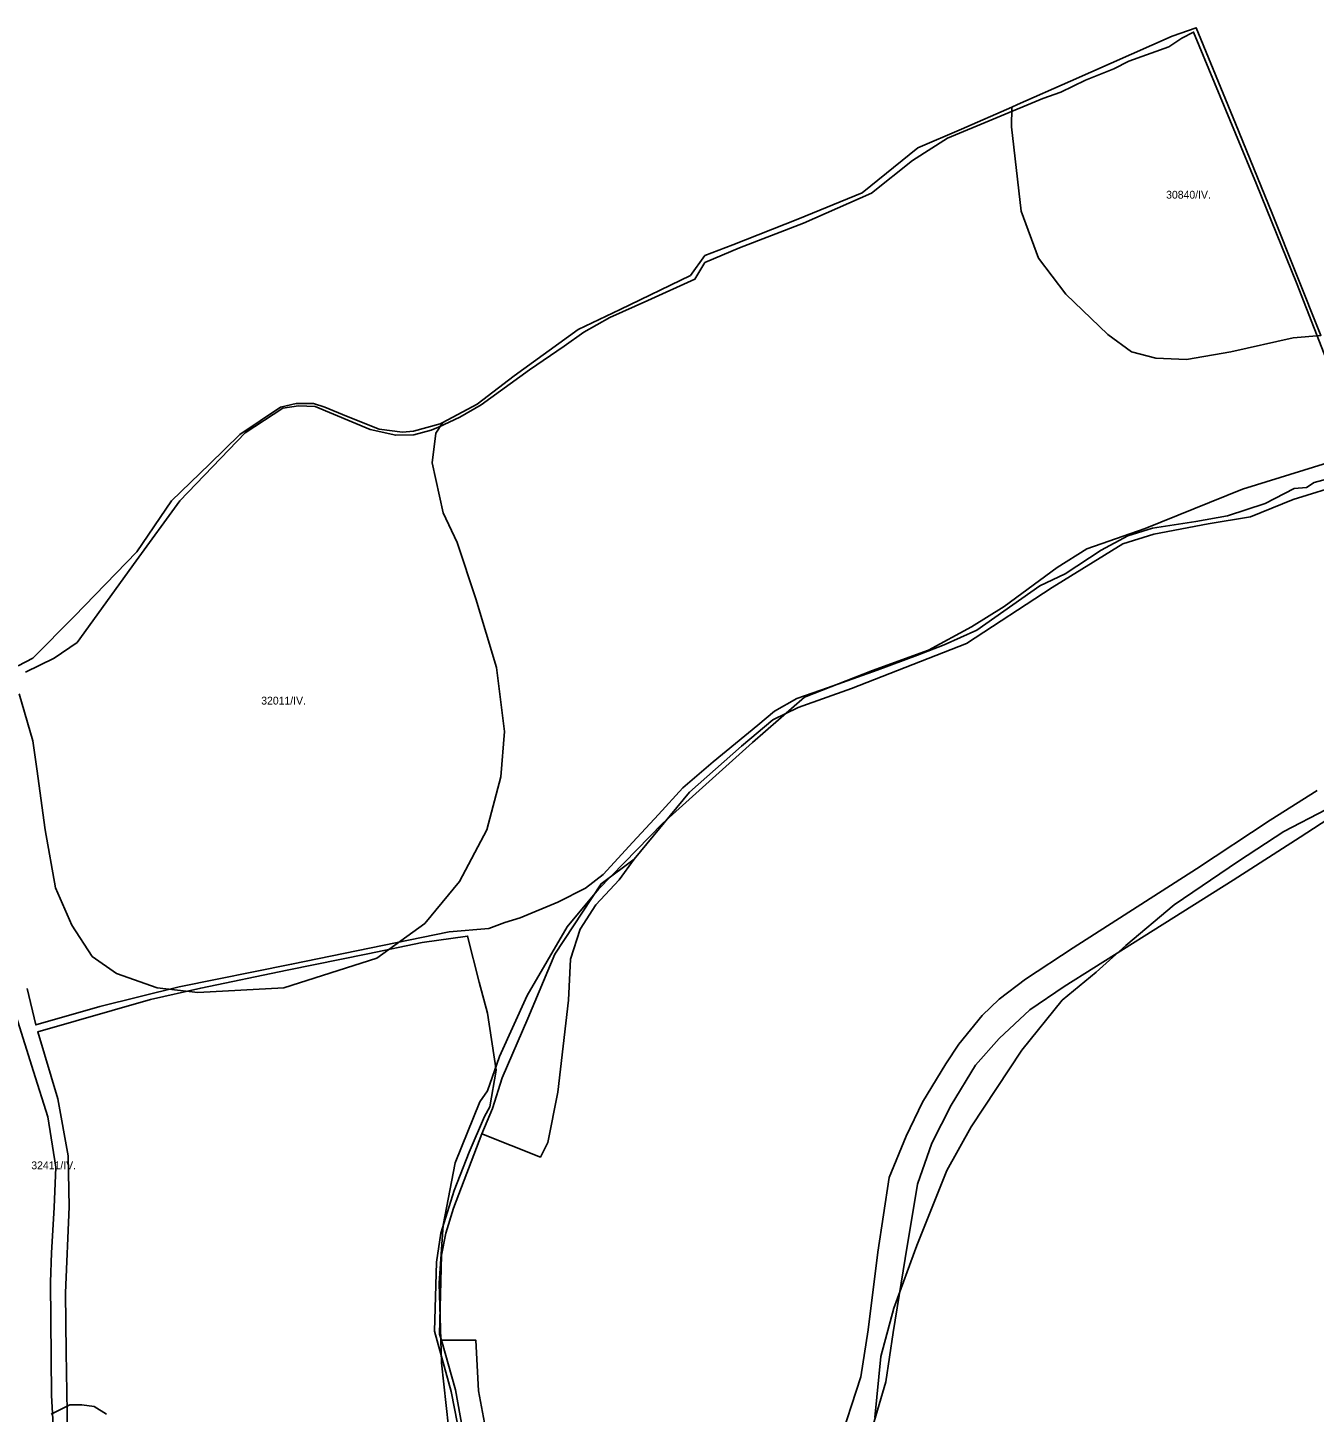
# Model space of a CAD drawing. Extents: x -532083 to -529270, y -1180561 to -1176456.
# Drawn here: x -531031 to -530208, y -1177342 to -1176456 of the extents above; entities that cross this region are included whole.
import ezdxf

# ---------------------------------------------------------------- set-up
doc = ezdxf.new("R2010")
doc.units = 0
for name, color, linetype in [('95560013', 7, 'Continuous'), ('95620013', 7, 'Continuous'), ('95660013', 7, 'Continuous')]:
    doc.layers.add(name, color=color, linetype=linetype)

msp = doc.modelspace()

# ---------------------------------------------------------------- linework, layer by layer
at = {"layer": '95560013'}
for points in [[(-531032.6033, -1176868.07145), (-531014.2283, -1176859.15945), (-530999.4883, -1176849.03245), (-530961.8023, -1176796.80545), (-530933.9613, -1176758.42645), (-530892.0933, -1176714.76745), (-530867.9773, -1176699.04445), (-530857.8783, -1176697.53245), (-530847.3283, -1176697.98545), (-530812.1553, -1176712.75345), (-530795.7153, -1176716.36145), (-530784.0703, -1176716.18945), (-530772.9393, -1176713.09745), (-530768.3153, -1176711.20745), (-530754.6163, -1176704.85245), (-530740.9163, -1176696.95045), (-530710.0913, -1176674.44745), (-530687.8533, -1176659.43745), (-530675.3193, -1176650.36945), (-530658.6773, -1176641.09545), (-530634.4323, -1176630.17245), (-530604.2293, -1176616.56945), (-530597.8603, -1176605.85345), (-530575.7753, -1176596.39745), (-530534.6893, -1176580.56545), (-530491.0983, -1176561.46745), (-530465.0443, -1176540.61045), (-530442.4973, -1176526.28645), (-530381.5713, -1176500.80145), (-530369.9723, -1176496.85745), (-530354.2443, -1176489.16645), (-530336.1573, -1176481.87045), (-530326.5243, -1176476.94045), (-530300.9663, -1176467.86945), (-530292.5133, -1176462.15045), (-530285.0423, -1176458.40345), (-530244.8243, -1176555.64745), (-530219.0883, -1176618.78145), (-530190.1893, -1176693.25345)], [(-530173.8473, -1176737.54745), (-530207.9223, -1176746.61545), (-530212.7903, -1176749.75445), (-530220.6143, -1176750.45245), (-530239.2163, -1176760.04345), (-530263.4073, -1176767.95345), (-530283.6703, -1176771.51545), (-530311.2443, -1176775.91545), (-530327.1203, -1176780.73545), (-530344.2503, -1176789.95445), (-530367.2283, -1176805.04145), (-530383.5223, -1176812.79445), (-530423.7443, -1176841.13645), (-530444.7393, -1176850.58645), (-530461.6973, -1176857.06645), (-530487.5383, -1176866.78745), (-530519.3013, -1176878.12745), (-530538.9513, -1176884.87745), (-530553.2173, -1176892.97745), (-530563.9843, -1176901.88745), (-530592.5173, -1176925.37745), (-530611.8973, -1176942.11845), (-530627.5313, -1176959.11045), (-530643.8413, -1176976.90845), (-530663.0183, -1176997.58245), (-530674.3093, -1177006.39145), (-530691.8723, -1177015.20045), (-530716.0683, -1177025.26745), (-530725.9253, -1177028.32345), (-530736.1553, -1177032.04745), (-530761.3993, -1177034.12845), (-530862.3733, -1177054.94045), (-530934.3013, -1177069.50945), (-530985.1343, -1177081.99645), (-531026.1123, -1177093.83845), (-531031.6673, -1177070.43545)], [(-530738.3213, -1177351.91345), (-530742.6713, -1177327.91645), (-530744.3633, -1177295.67845), (-530766.3533, -1177295.67845), (-530767.7883, -1177291.65545), (-530767.0563, -1177266.43445), (-530766.3243, -1177241.21445), (-530763.6393, -1177227.01245), (-530758.7563, -1177211.09645), (-530740.6923, -1177163.59445), (-530703.0453, -1177178.44445), (-530698.4073, -1177169.14045), (-530691.9853, -1177136.93445), (-530685.2073, -1177077.89045), (-530683.7803, -1177051.76745), (-530677.7163, -1177032.44445), (-530667.7273, -1177017.05645), (-530652.7433, -1177000.95345), (-530643.1113, -1176987.71345), (-530607.5943, -1176944.85845), (-530574.4383, -1176915.34545), (-530554.2373, -1176898.60645), (-530538.2083, -1176890.67745), (-530503.9553, -1176878.56345), (-530430.3583, -1176849.77845), (-530375.6313, -1176813.86345), (-530330.4023, -1176785.82645), (-530310.5013, -1176779.79645), (-530275.6753, -1176773.14245), (-530248.5193, -1176768.56745), (-530221.3573, -1176757.56345), (-530188.3163, -1176747.18245)], [(-530490.6373, -1177351.35145), (-530481.9833, -1177322.15245), (-530477.2563, -1177290.69245), (-530469.5993, -1177243.23545), (-530461.6683, -1177195.77945), (-530452.6443, -1177169.44545), (-530440.2693, -1177145.16045), (-530424.5623, -1177119.55645), (-530409.5093, -1177102.48845), (-530389.8753, -1177084.10645), (-530367.8413, -1177069.22645), (-530310.9193, -1177033.44145), (-530259.8063, -1177001.26645), (-530216.7773, -1176973.53945), (-530159.4063, -1176936.39445)], [(-530205.9203, -1176943.67145), (-530236.1413, -1176962.81445), (-530283.1843, -1176993.94545), (-530362.1843, -1177044.41145), (-530392.5373, -1177064.43045), (-530409.5853, -1177077.36045), (-530420.3953, -1177087.78645), (-530435.3643, -1177106.13845), (-530443.6803, -1177118.65045), (-530458.6483, -1177143.25745), (-530469.0433, -1177164.94545), (-530479.9283, -1177191.48345), (-530487.1233, -1177239.29545), (-530493.4183, -1177288.91245), (-530497.9153, -1177319.13345), (-530512.7543, -1177364.23845)], [(-531005.7623, -1177354.41745), (-531006.6203, -1177303.21945), (-531007.0673, -1177265.32145), (-531004.6083, -1177210.15545), (-531005.4483, -1177177.64145), (-531011.8923, -1177141.08845), (-531024.7793, -1177098.29545), (-530952.6283, -1177077.48645), (-530920.4683, -1177070.20245), (-530865.1403, -1177058.75645), (-530813.6153, -1177048.35045), (-530778.6893, -1177041.06545), (-530749.7013, -1177036.94645), (-530742.3883, -1177066.49945), (-530736.9553, -1177086.20145), (-530731.3133, -1177122.67145), (-530735.4923, -1177146.14645), (-530738.8923, -1177152.46045), (-530748.7013, -1177175.24545), (-530758.2523, -1177199.84445), (-530766.7703, -1177227.03145), (-530769.6093, -1177245.67445), (-530770.9653, -1177289.89945), (-530760.1993, -1177328.34445), (-530756.1083, -1177349.07945)], [(-531043.1993, -1177073.95245), (-531027.6233, -1177123.57445), (-531018.2733, -1177152.67245), (-531013.2393, -1177184.89645), (-531014.1983, -1177210.62345), (-531016.1163, -1177239.72145), (-531016.5953, -1177258.47845), (-531016.1163, -1177330.85845), (-531013.9583, -1177369.33145)], [(-530753.0623, -1177352.39845), (-530757.4123, -1177327.43145), (-530766.3533, -1177295.67845), (-530744.3633, -1177295.67845), (-530742.6713, -1177327.91645), (-530738.3213, -1177351.91345)]]:
    msp.add_lwpolyline(points, dxfattribs=at)
at = {"layer": '95620013'}
msp.add_lwpolyline([(-530703.0453, -1177178.44445), (-530740.6923, -1177163.59445), (-530733.7253, -1177147.31145), (-530727.6603, -1177127.63045), (-530711.2503, -1177089.69845), (-530693.7693, -1177048.54745), (-530664.1593, -1177003.45845), (-530643.1113, -1176987.71345), (-530652.7433, -1177000.95345), (-530667.7273, -1177017.05645), (-530677.7163, -1177032.44445), (-530683.7803, -1177051.76745), (-530685.2073, -1177077.89045), (-530691.9853, -1177136.93445), (-530698.4073, -1177169.14045)], close=True, dxfattribs=at)
at = {"layer": '95660013'}
msp.add_lwpolyline([(-530339.8753, -1176652.00045), (-530366.8123, -1176626.00045), (-530384.3753, -1176603.00045), (-530395.5003, -1176573.00045), (-530401.6873, -1176519.00045), (-530401.4093, -1176506.37645), (-530397.7873, -1176504.78445), (-530363.8373, -1176489.74845), (-530298.8543, -1176460.89445), (-530283.3013, -1176455.55145), (-530258.2053, -1176516.84145), (-530234.7283, -1176574.37945), (-530203.5463, -1176652.48045), (-530221.3123, -1176654.00045), (-530261.1873, -1176663.00045), (-530289.6253, -1176668.00045), (-530309.3123, -1176667.00045), (-530324.8753, -1176663.00045)], close=True, dxfattribs=at)
for points in [[(-531036.8123, -1176882.00045), (-531027.8753, -1176912.00045), (-531025.3123, -1176930.00045), (-531020.1253, -1176969.00045), (-531013.3753, -1177006.00045), (-531003.0003, -1177030.00045), (-530990.0003, -1177050.00045), (-530974.3753, -1177061.00045), (-530948.3753, -1177070.00045), (-530922.3753, -1177073.00045), (-530867.3753, -1177070.00045), (-530807.8753, -1177051.00045), (-530777.1253, -1177029.00045), (-530754.8123, -1177002.00045), (-530737.3753, -1176969.00045), (-530728.3753, -1176935.00045), (-530726.1873, -1176906.00045), (-530731.1253, -1176865.00045), (-530744.3753, -1176821.00045), (-530756.3123, -1176785.00045), (-530765.3123, -1176766.00045), (-530772.3123, -1176734.00045), (-530770.1253, -1176715.00045), (-530765.5203, -1176708.21745), (-530743.4693, -1176696.60945), (-530719.8803, -1176678.38845), (-530678.8353, -1176648.80945), (-530651.9913, -1176635.85945), (-530607.0953, -1176614.09445), (-530597.8583, -1176601.38045), (-530580.0163, -1176594.47545), (-530538.3833, -1176578.04345), (-530497.0913, -1176561.26945), (-530461.6013, -1176532.51345), (-530433.6183, -1176520.53145), (-530401.4093, -1176506.37645), (-530401.6873, -1176519.00045), (-530395.5003, -1176573.00045), (-530384.3753, -1176603.00045), (-530366.8123, -1176626.00045), (-530339.8753, -1176652.00045), (-530324.8753, -1176663.00045), (-530309.3123, -1176667.00045), (-530289.6253, -1176668.00045), (-530261.1873, -1176663.00045), (-530221.3123, -1176654.00045), (-530203.5463, -1176652.48045)], [(-531037.3783, -1176863.89245), (-531027.9683, -1176858.99445), (-531001.5763, -1176832.37245), (-530961.3773, -1176791.01345), (-530939.2173, -1176758.44245), (-530914.7843, -1176734.87645), (-530895.5463, -1176715.94245), (-530869.4123, -1176698.46445), (-530859.4313, -1176696.09745), (-530848.3603, -1176696.09745), (-530841.1003, -1176698.46445), (-530827.3073, -1176704.29045), (-530806.2153, -1176712.46345), (-530791.3543, -1176714.35645), (-530784.2773, -1176713.88345), (-530767.2933, -1176709.15145), (-530765.5213, -1176708.21845), (-530770.1253, -1176715.00045), (-530772.3123, -1176734.00045), (-530765.3123, -1176766.00045), (-530756.3123, -1176785.00045), (-530744.3753, -1176821.00045), (-530731.1253, -1176865.00045), (-530726.1873, -1176906.00045), (-530728.3753, -1176935.00045), (-530737.3753, -1176969.00045), (-530754.8123, -1177002.00045), (-530777.1253, -1177029.00045), (-530807.8753, -1177051.00045), (-530867.3753, -1177070.00045), (-530922.3753, -1177073.00045), (-530948.3753, -1177070.00045), (-530974.3753, -1177061.00045), (-530990.0003, -1177050.00045), (-531003.0003, -1177030.00045), (-531013.3753, -1177006.00045), (-531020.1253, -1176969.00045), (-531025.3123, -1176930.00045), (-531027.8753, -1176912.00045), (-531036.8123, -1176882.00045)], [(-530199.3753, -1176734.00045), (-530253.6873, -1176751.00045), (-530316.1253, -1176776.00045), (-530353.3753, -1176789.00045), (-530372.3123, -1176801.00045), (-530406.3123, -1176826.00045), (-530427.1873, -1176839.00045), (-530454.6873, -1176854.00045), (-530490.6253, -1176867.00045), (-530534.1253, -1176884.00045), (-530567.3753, -1176913.00045), (-530624.8753, -1176965.00045), (-530665.8123, -1177007.00045), (-530686.0003, -1177031.00045), (-530711.5003, -1177075.00045), (-530729.1873, -1177114.00045), (-530737.0003, -1177136.00045), (-530741.8753, -1177143.00045), (-530757.6253, -1177182.00045), (-530765.3753, -1177222.00045), (-530767.8123, -1177259.00045), (-530766.3753, -1177310.00045), (-530761.8753, -1177351.00045)], [(-530761.8753, -1177351.00045), (-530766.3753, -1177310.00045), (-530767.8123, -1177259.00045), (-530765.3753, -1177222.00045), (-530757.6253, -1177182.00045), (-530741.8753, -1177143.00045), (-530737.0003, -1177136.00045), (-530729.1873, -1177114.00045), (-530711.5003, -1177075.00045), (-530686.0003, -1177031.00045), (-530665.8123, -1177007.00045), (-530624.8753, -1176965.00045), (-530567.3753, -1176913.00045), (-530534.1253, -1176884.00045), (-530490.6253, -1176867.00045), (-530454.6873, -1176854.00045), (-530427.1873, -1176839.00045), (-530406.3123, -1176826.00045), (-530372.3123, -1176801.00045), (-530353.3753, -1176789.00045), (-530316.1253, -1176776.00045), (-530253.6873, -1176751.00045), (-530199.3753, -1176734.00045)], [(-530489.1253, -1177345.00045), (-530485.1253, -1177306.00045), (-530476.8123, -1177275.00045), (-530462.1873, -1177235.00045), (-530443.0003, -1177187.00045), (-530427.3753, -1177159.00045), (-530394.8753, -1177110.00045), (-530369.1253, -1177078.00045), (-530347.5003, -1177060.00045), (-530328.3123, -1177043.00045), (-530297.5003, -1177017.00045), (-530256.3753, -1176989.00045), (-530227.1873, -1176970.00045), (-530200.1253, -1176956.00045)], [(-530200.1253, -1176956.00045), (-530227.1873, -1176970.00045), (-530256.3753, -1176989.00045), (-530297.5003, -1177017.00045), (-530328.3123, -1177043.00045), (-530347.5003, -1177060.00045), (-530369.1253, -1177078.00045), (-530394.8753, -1177110.00045), (-530427.3753, -1177159.00045), (-530443.0003, -1177187.00045), (-530462.1873, -1177235.00045), (-530476.8123, -1177275.00045), (-530485.1253, -1177306.00045), (-530489.1253, -1177345.00045)], [(-530980.8123, -1177343.00045), (-530988.6253, -1177338.00045), (-530996.5003, -1177337.00045), (-531004.3123, -1177337.00045), (-531016.1253, -1177343.00045)], [(-531016.1253, -1177343.00045), (-531004.3123, -1177337.00045), (-530996.5003, -1177337.00045), (-530988.6253, -1177338.00045), (-530980.8123, -1177343.00045)]]:
    msp.add_lwpolyline(points, dxfattribs=at)

# ---------------------------------------------------------------- texts
for s, rotation, p in [('30840/IV.', 0.00000004, (-530302.6168, -1176564.95282)), ('32011/IV.', 0.00000001, (-530881.7828, -1176888.76198)), ('32411/IV.', 359.99999998, (-531028.93999, -1177186.18845))]:
    msp.add_text(s, height=5, rotation=rotation, dxfattribs=at).set_placement(p)

doc.saveas('drawing.dxf')
